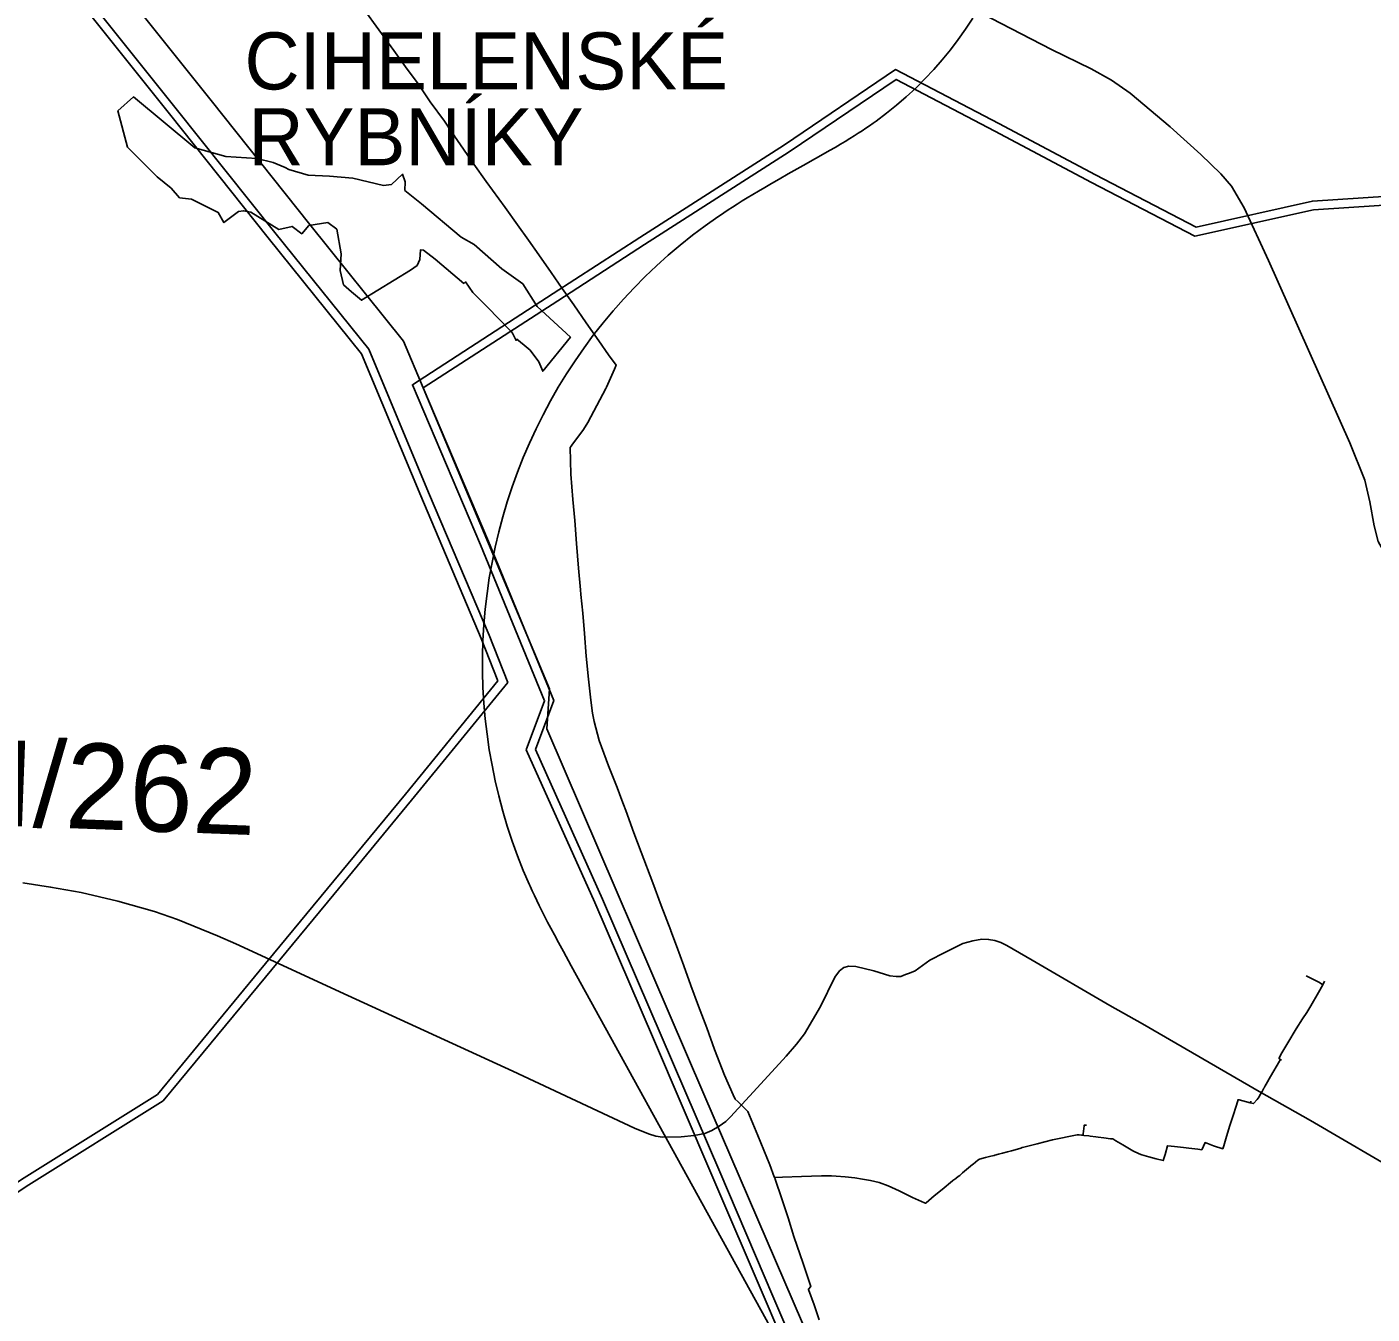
# Model space of a CAD drawing. Extents: x -789162 to -606354, y -1062736 to -945481.
# Drawn here: x -728880 to -726523, y -978118 to -975863 of the extents above; entities that cross this region are included whole.
import ezdxf

# ---------------------------------------------------------------- set-up
doc = ezdxf.new("R2010")
doc.units = 0
for name, color, linetype in [('_SIRSI VZTAHY_ELEKTRICKE VEDENI VN 110 kV N', 7, 'Continuous'), ('_SIRSI VZTAHY_ELEKTRICKE VEDENI VN 110 kV S', 7, 'Continuous'), ('_SIRSI VZTAHY_NATURA_EVL', 7, 'Continuous'), ('_SIRSI VZTAHY_NATURA_EVL_POPIS_KOD', 7, 'Continuous'), ('_SIRSI VZTAHY_SILNICE I TRIDY_NAVRH', 7, 'Continuous'), ('_SIRSI VZTAHY_SILNICE II TRIDY_STAV', 7, 'Continuous'), ('_SIRSI VZTAHY_SILNICE III TRIDY_STAV', 7, 'Continuous'), ('_SIRSI VZTAHY_SILNICE_STAV_POPIS', 7, 'Continuous'), ('_SIRSI VZTAHY_VTL PLYNOVOD', 7, 'Continuous')]:
    doc.layers.add(name, color=color, linetype=linetype)

msp = doc.modelspace()

# ---------------------------------------------------------------- linework, layer by layer
at = {"layer": '_SIRSI VZTAHY_ELEKTRICKE VEDENI VN 110 kV N'}
for points in [[(-730001.6, -974182.2), (-729926.4, -974276.7), (-729753.9, -974490.2), (-729579.2, -974709.3), (-729405.6, -974927.8), (-729235.3, -975141.2), (-729082, -975332.9), (-728912.9, -975546.4), (-728734.6, -975769.6), (-728557.1, -975992.1), (-728384.2, -976209.3), (-728219.7, -976413.6), (-728185.4, -976495.7)], [(-727043.5, -979221.4), (-727144.6, -978951.3), (-727261.2, -978729.6), (-727314.8, -978612.5), (-727442.5, -978315.6), (-727693.4, -977732.6), (-727968.8, -977092.7), (-727963.8, -977022.8), (-728185.4, -976495.7)]]:
    msp.add_lwpolyline(points, dxfattribs=at)
at = {"layer": '_SIRSI VZTAHY_ELEKTRICKE VEDENI VN 110 kV S'}
for points in [[(-728807.1, -975793.2), (-728629.6, -976015.7), (-728456.8, -976232.9), (-728293.4, -976435.6), (-728189.6, -976684.6), (-728083.6, -976934.7), (-728054.5, -977008.8)], [(-728795.4, -975783.9), (-728617.9, -976006.4), (-728445, -976223.5), (-728280.5, -976427.8), (-728175.9, -976678.6), (-728069.9, -976928.7), (-728036.8, -977011.8)], [(-725022.1, -976234.6), (-725022.2, -976234.6), (-725057, -976205.9), (-725103.2, -976186.7), (-725220.4, -976141.5), (-725361.8, -976086.8), (-725625.8, -976104.5), (-725922, -976124.3), (-726203.4, -976142), (-726405.2, -976153.7), (-726627.4, -976168.4), (-726831.3, -976213.7), (-727007.7, -976122.3), (-727177, -976032.2), (-727357.7, -975937.8), (-727552.2, -976069.5), (-727806, -976231.8), (-727957.6, -976330.3), (-728204.2, -976489.9), (-728084.9, -976770.4), (-727972.7, -977043.6), (-728004.9, -977129.4)], [(-725022.1, -976234.7), (-725022.2, -976234.7), (-725062.8, -976222.5), (-725109.1, -976200.4), (-725225.8, -976155.5), (-725364.1, -976102), (-725624.8, -976119.5), (-725921, -976139.3), (-726202.5, -976157), (-726404.2, -976168.7), (-726625.3, -976183.3), (-726833.4, -976229.5), (-727014.7, -976135.5), (-727184, -976045.5), (-727356.7, -975955.2), (-727544, -976082.1), (-727797.9, -976244.4), (-727949.5, -976342.9), (-728185.4, -976495.7), (-728071, -976764.6), (-727956.6, -977043.3), (-727988.7, -977129)], [(-728054.5, -977008.8), (-728216.6, -977207.2), (-728353.2, -977372.6), (-728472.7, -977517.6), (-728651, -977733.2), (-728884.3, -977879.2), (-729090.9, -978015.6), (-729298.2, -978150.3), (-729594, -978336.2), (-729816.7, -978480.8), (-730030.3, -978616.1), (-729984.7, -978878.1), (-729928.4, -979207.9), (-729879.9, -979486.1), (-730037.7, -979666.1), (-730181.7, -979830.4), (-730322.2, -979989.1), (-730471.5, -980157.9), (-730642.9, -980353.2), (-730823, -980555.3), (-731005.8, -980762.6), (-730973.3, -980973.9)], [(-728036.8, -977011.8), (-728205.6, -977217.5), (-728342.2, -977382.8), (-728461.7, -977527.7), (-728641.2, -977744.7), (-728876.1, -977891.8), (-729082.6, -978028.1), (-729289.9, -978162.8), (-729585.8, -978348.7), (-729808.5, -978493.3), (-730014, -978623.5), (-729969.9, -978875.8), (-729913.6, -979205.4), (-729864, -979490.8), (-730026.5, -979676.1), (-730170.4, -979840.4), (-730311, -979999.1), (-730460.3, -980167.9), (-730631.7, -980363.1), (-730811.7, -980565.1), (-730990.1, -980767.3), (-730957.1, -980982.4)], [(-727092.7, -979228.6), (-727080.3, -979163.2), (-727226.1, -978879.4), (-727350.5, -978612.4), (-727484, -978332), (-727586.5, -978092.8), (-727679.6, -977874.8), (-727782.1, -977635.9), (-727884.9, -977397), (-728004.9, -977129.4)], [(-727045.2, -979222.6), (-727045.2, -979222.7), (-727045.6, -979222.7), (-727046.3, -979224.3), (-727072.1, -979261.5), (-727076.9, -979225.8), (-727065.1, -979159.9), (-727212.6, -978872.9), (-727337, -978605.9), (-727470.4, -978325.8), (-727572.7, -978086.9), (-727665.8, -977868.9), (-727768.3, -977630), (-727871.2, -977391.1), (-727988.7, -977129)]]:
    msp.add_lwpolyline(points, dxfattribs=at)
at = {"layer": '_SIRSI VZTAHY_NATURA_EVL'}
msp.add_lwpolyline([(-728073.1, -976353.3), (-728030.5, -976397.6), (-728028.9, -976399.8), (-728022.6, -976412.4), (-728021.4, -976410.3), (-728008.5, -976420.4), (-727998, -976429.3), (-727982.8, -976449.6), (-727976, -976466.3), (-727927.4, -976406.7), (-727985.9, -976352.8), (-728010.6, -976313.3), (-728047.5, -976286.9), (-728095.8, -976244.2), (-728119, -976231.3), (-728188.1, -976173), (-728217.5, -976149.6), (-728216.7, -976134.8), (-728221.6, -976121.3), (-728241.1, -976139.4), (-728255.1, -976140.8), (-728308.8, -976128.3), (-728349.7, -976124.6), (-728386.9, -976123.1), (-728420.7, -976113.2), (-728427.3, -976109.2), (-728448.2, -976100.6), (-728477.1, -976093.9), (-728531.1, -976090.3), (-728585.4, -976075.2), (-728692.7, -975985.8), (-728720.5, -976010.1), (-728703.3, -976073.9), (-728651.7, -976126), (-728626.9, -976145.4), (-728612.1, -976162.6), (-728591.5, -976165), (-728544.3, -976188.5), (-728534.5, -976205.9), (-728509, -976186.6), (-728500, -976185.1), (-728487.5, -976187.9), (-728438.1, -976217.9), (-728415.1, -976212.6), (-728398.2, -976225.6), (-728385.6, -976210.9), (-728352.4, -976205.7), (-728336.8, -976217.7), (-728329, -976260.6), (-728330.7, -976289.7), (-728325.1, -976314.7), (-728310.7, -976327.1), (-728293.2, -976341.9), (-728207.5, -976289.1), (-728196, -976281.3), (-728191.3, -976270.7), (-728189.9, -976253.5), (-728184.7, -976254), (-728164.4, -976270.2), (-728114, -976312.4), (-728111, -976310), (-728098.2, -976328.2)], close=True, dxfattribs=at)
at = {"layer": '_SIRSI VZTAHY_SILNICE I TRIDY_NAVRH'}
msp.add_lwpolyline([(-727222.6, -975847.9), (-727235, -975866.8), (-727248, -975885.3), (-727261.7, -975903.3), (-727276, -975920.8), (-727290.9, -975937.8), (-727306.4, -975954.3), (-727322.4, -975970.2), (-727339, -975985.5), (-727356.1, -976000.3), (-727373.7, -976014.5), (-727391.8, -976028), (-727397.3, -976031.9), (-727403.4, -976036.2), (-727409.8, -976040.6), (-727416.4, -976045), (-727423.3, -976049.5), (-727430.4, -976054), (-727437.9, -976058.8), (-727445.9, -976063.6), (-727454.3, -976068.7), (-727463.4, -976074.1), (-727473.3, -976079.9), (-727484.5, -976086.3), (-727497.9, -976093.9), (-727519.7, -976106.1), (-727545.7, -976120.7), (-727561.8, -976129.8), (-727575.2, -976137.4), (-727587, -976144.3), (-727597.9, -976150.7), (-727608, -976156.7), (-727617.5, -976162.5), (-727626.5, -976168), (-727635.1, -976173.4), (-727643.4, -976178.7), (-727651.3, -976183.8), (-727658.9, -976188.9), (-727666.3, -976193.9), (-727669.2, -976195.8), (-727691.6, -976211.7), (-727713.6, -976228.2), (-727735.1, -976245.4), (-727756, -976263.2), (-727776.5, -976281.5), (-727796.4, -976300.5), (-727815.8, -976320), (-727834.5, -976340.1), (-727852.7, -976360.7), (-727870.3, -976381.8), (-727887.3, -976403.4), (-727903.6, -976425.5), (-727919.3, -976448.1), (-727934.3, -976471.1), (-727948.7, -976494.5), (-727962.4, -976518.4), (-727975.3, -976542.6), (-727987.6, -976567.2), (-727999.2, -976592.1), (-728010, -976617.4), (-728020.1, -976643), (-728029.4, -976668.8), (-728038, -976694.9), (-728045.9, -976721.2), (-728053, -976747.8), (-728059.3, -976774.6), (-728064.8, -976801.5), (-728069.5, -976828.5), (-728073.5, -976855.7), (-728076.7, -976883), (-728079, -976910.4), (-728080.6, -976937.9), (-728081.4, -976965.3), (-728081.4, -976992.8), (-728080.6, -977020.3), (-728079, -977047.7), (-728076.7, -977075.1), (-728073.5, -977102.4), (-728069.5, -977129.6), (-728064.8, -977156.7), (-728059.2, -977183.6), (-728052.9, -977210.4), (-728045.9, -977236.9), (-728038, -977263.3), (-728029.4, -977289.4), (-728020.1, -977315.2), (-728010, -977340.8), (-727999.1, -977366), (-727998.1, -977368.4), (-727994.4, -977376.5), (-727990.5, -977384.9), (-727986.4, -977393.4), (-727982.1, -977402.3), (-727977.5, -977411.5), (-727972.6, -977421.2), (-727967.4, -977431.3), (-727961.7, -977442.2), (-727955.5, -977453.9), (-727948.4, -977467.1), (-727939.8, -977482.8), (-727925.9, -977508.2), (-727399.4, -978463.4)], dxfattribs=at)
at = {"layer": '_SIRSI VZTAHY_SILNICE II TRIDY_STAV'}
msp.add_lwpolyline([(-726460.9, -977878), (-726630.6, -977779.2), (-726720.9, -977728.4), (-726925.1, -977609.8), (-726982.4, -977577.5), (-727118.3, -977497.9), (-727162.6, -977472.1), (-727173.3, -977466.9), (-727184.1, -977463.7), (-727194.7, -977461.8), (-727206.4, -977461.4), (-727222.4, -977464.2), (-727240.1, -977469.1), (-727272.6, -977485.1), (-727298, -977498.2), (-727323.2, -977516.5), (-727333.2, -977520.6), (-727340.2, -977523.4), (-727348.8, -977526.5), (-727356.6, -977526.8), (-727368.1, -977525.3), (-727395.8, -977516.6), (-727427.4, -977509), (-727439.4, -977508.7), (-727448.2, -977511.1), (-727456, -977516.5), (-727464.4, -977528), (-727489.1, -977579.2), (-727517.4, -977627.3), (-727531.2, -977645.1), (-727549.7, -977666.2), (-727600.2, -977721.5), (-727647, -977772.4), (-727655.4, -977780.7), (-727666.7, -977788.7), (-727679.5, -977796.4), (-727691.7, -977801.6), (-727710.9, -977805.2), (-727733.4, -977807.5), (-727766.3, -977807.9), (-727778, -977806.1), (-727790.4, -977802.2), (-727815.4, -977792.3), (-728028.1, -977692.7), (-728317.4, -977559.9), (-728513.8, -977469.6), (-728545.5, -977455.6), (-728616, -977426.9), (-728656.2, -977412.9), (-728720.5, -977394.6), (-728784.6, -977379.6), (-728838.2, -977370), (-728886.8, -977362.3)], dxfattribs=at)
at = {"layer": '_SIRSI VZTAHY_SILNICE III TRIDY_STAV'}
msp.add_lwpolyline([(-727226, -975829.8), (-727084.3, -975902.6), (-727015, -975936.8), (-726979.4, -975956.2), (-726946.6, -975979.2), (-726876.7, -976038.4), (-726823.2, -976086.6), (-726788.1, -976120.4), (-726769.1, -976142.4), (-726746.8, -976179.9), (-726704.2, -976272.2), (-726562.2, -976591.7), (-726535.4, -976657.2), (-726526.7, -976694.9), (-726519.5, -976736.9), (-726512.2, -976764.7), (-726498.9, -976788.6), (-726463.7, -976828.5), (-726425.6, -976870), (-726387.7, -976903.2), (-726199.4, -977071.6), (-726010.4, -977249.1), (-725963.6, -977296.5), (-725896.6, -977368.5)], dxfattribs=at)
at = {"layer": '_SIRSI VZTAHY_VTL PLYNOVOD'}
for points in [[(-728289.2, -975832), (-728263.1, -975868), (-728237, -975904.4), (-728216.6, -975933), (-728194.4, -975962.9), (-728172.9, -975994.1), (-728148, -976028.3), (-728135.7, -976046.7), (-728130.7, -976054.2), (-728130.5, -976054.5), (-728120.1, -976069.9), (-728096.6, -976103.3), (-728075.1, -976133.7), (-728041.6, -976179.7), (-728020.3, -976209.8), (-728001.1, -976237), (-727982.6, -976262.6), (-727961.4, -976293.1), (-727941.7, -976321.5), (-727921.5, -976349.9), (-727899.9, -976381.3), (-727877.9, -976413), (-727860.7, -976437.4), (-727847.4, -976455.9), (-727850.4, -976462.9), (-727864.1, -976494.2), (-727865.4, -976496.7), (-727897.1, -976556.1), (-727904.7, -976568.5), (-727924.7, -976595.8), (-727926, -976597.6), (-727927.9, -976600.1), (-727926.7, -976646.7), (-727923.2, -976690.8), (-727919.8, -976727.7), (-727916.7, -976768), (-727913.1, -976811.1), (-727909.6, -976849.4), (-727908.9, -976857.2), (-727905.7, -976889.9), (-727902.6, -976925.7), (-727900, -976965.4), (-727895.8, -977005.7), (-727891.5, -977042.5), (-727888.5, -977065.2), (-727886, -977080), (-727877, -977113.4), (-727860.8, -977157.8), (-727845.8, -977195.8), (-727837.2, -977218), (-727834.5, -977225.1), (-727830.4, -977235.8), (-727816.1, -977274.9), (-727803.4, -977308.9), (-727783.1, -977362.5), (-727768.3, -977402.2), (-727751.6, -977446), (-727751.3, -977446.8), (-727741.7, -977472.8), (-727728.8, -977507.9), (-727716.4, -977542.2), (-727703, -977578.8), (-727688.6, -977616.8), (-727674.9, -977654.8), (-727657.7, -977699.4), (-727642.2, -977734.1), (-727638.6, -977741.4), (-727633.8, -977746.1), (-727630.7, -977749.1), (-727625.4, -977754.3), (-727624.2, -977755.5), (-727624.1, -977755.7), (-727624.1, -977755.7), (-727618.3, -977761.2), (-727616.6, -977763.4), (-727599.2, -977805), (-727578.1, -977856.5), (-727570.2, -977877.8), (-727570.2, -977877.9), (-727570.1, -977878.1), (-727570, -977878.5), (-727569.9, -977878.7), (-727569.8, -977878.9)], [(-726683.5, -977672.1), (-726684.4, -977671.6), (-726685, -977671.3), (-726686.3, -977670.6), (-726686.2, -977670.3), (-726686, -977670), (-726685.7, -977669.4), (-726685.5, -977669), (-726680.8, -977660.3), (-726667.2, -977637), (-726659.4, -977624.3), (-726655.9, -977618.5), (-726644.8, -977601.1), (-726637.2, -977589.6), (-726630.1, -977578), (-726616.7, -977554.6), (-726609.4, -977541)], [(-726614.8, -977537.6), (-726615.3, -977537.3), (-726638.4, -977525.5), (-726638.7, -977525.4)], [(-726614.8, -977537.6), (-726614.5, -977537.2), (-726614.1, -977537.5), (-726613.8, -977537.7), (-726613.7, -977537.8), (-726614, -977538.2)], [(-726614.8, -977537.6), (-726614.4, -977537.9), (-726614.2, -977538), (-726614, -977538.2)], [(-726609.4, -977541), (-726613.6, -977538.5), (-726614, -977538.2)], [(-726609.4, -977541), (-726606.1, -977535.1)], [(-726736.4, -977747.9), (-726730.6, -977749.4), (-726724.1, -977741.9), (-726722.7, -977740.1), (-726721.9, -977739), (-726721.3, -977738.1), (-726721, -977737.6), (-726720, -977735.9), (-726715.6, -977728.1), (-726712.5, -977722.5), (-726711.7, -977721.3), (-726711.3, -977720.7), (-726710.1, -977718.3), (-726708.3, -977715.1), (-726701, -977701.9), (-726685.1, -977674.8), (-726684.6, -977673.9), (-726683.8, -977672.5), (-726683.6, -977672.3), (-726683.5, -977672.1)], [(-726683.5, -977672.1), (-726682.7, -977672.5), (-726682, -977672.8), (-726681.8, -977672.9), (-726681.7, -977672.9)], [(-727029.5, -977804.8), (-727029.2, -977804.8), (-727029, -977804.9), (-727028.5, -977804.9), (-727027.7, -977805), (-727019.2, -977806), (-727019.2, -977806), (-727016.8, -977806.3), (-727006.9, -977807.5), (-727002.9, -977808.1), (-726992.9, -977809.3), (-726981.3, -977810.8), (-726977.1, -977811), (-726975.1, -977812.2), (-726971.6, -977814.3), (-726959.8, -977821.4), (-726942.1, -977832), (-726931.1, -977837.6), (-726926.5, -977839.1), (-726913.8, -977842.8), (-726901.2, -977846), (-726888.7, -977849.3), (-726885.6, -977838.5), (-726881.3, -977823.1), (-726880.9, -977823.2), (-726868.9, -977824.3), (-726853.2, -977826.5), (-726843.9, -977827.5), (-726828.4, -977829.3), (-726821.3, -977830.2), (-726815.4, -977817.5), (-726800.8, -977823.1), (-726784.6, -977828.5), (-726782.8, -977823.5), (-726779.2, -977810.8), (-726772.6, -977789.6), (-726766.8, -977772.2), (-726760.6, -977752), (-726757.5, -977742.2), (-726756.7, -977742.5), (-726756, -977742.9), (-726736.4, -977747.9)], [(-726736.4, -977747.9), (-726735.6, -977745.5), (-726735.5, -977745.1)], [(-727568.6, -977879), (-727568.2, -977878.8), (-727567.7, -977878.6), (-727555.9, -977878.4), (-727522.3, -977877.2), (-727487.7, -977875.8), (-727481.1, -977875.9), (-727470.3, -977876.1), (-727461.8, -977876.6), (-727446, -977877.7), (-727429.2, -977879.5), (-727415.9, -977881.5), (-727401.7, -977884.1), (-727386.4, -977887.8), (-727370.9, -977893.5), (-727351.7, -977902.4), (-727327.9, -977913.6), (-727307.2, -977923.2), (-727305.5, -977924), (-727304.3, -977923.4), (-727290.3, -977911), (-727275.9, -977899.9), (-727258, -977884.9), (-727257.6, -977884.7), (-727257.2, -977884.3), (-727252.3, -977880.4), (-727251.5, -977879.8), (-727247.9, -977876.9), (-727245.4, -977875), (-727241.9, -977871.9), (-727241.3, -977871.4), (-727240.6, -977870.9), (-727240.5, -977870.9), (-727222.8, -977856.1), (-727221.6, -977855.2), (-727213.4, -977848.5), (-727210.9, -977846.5), (-727200.5, -977843.9), (-727193, -977842), (-727185.6, -977840.2), (-727185, -977840), (-727184.1, -977839.8), (-727177.7, -977838), (-727170.7, -977836.1), (-727170.6, -977836.1), (-727161.6, -977833.7), (-727154.5, -977831.8), (-727140, -977827.8), (-727139.9, -977827.8), (-727138.4, -977827.3), (-727135.9, -977826.5), (-727133.2, -977825.9), (-727109.7, -977819.8), (-727083, -977812.6), (-727083, -977812.6), (-727039.6, -977804), (-727035.9, -977804), (-727032, -977804.5), (-727030.2, -977804.7), (-727029.9, -977804.7)], [(-727029.5, -977804.6), (-727029.9, -977804.6), (-727029.9, -977804.7), (-727029.9, -977804.7)], [(-727029.9, -977804.7), (-727029.5, -977804.8)], [(-727023.2, -977787.2), (-727024, -977787.2), (-727024, -977787.2), (-727024.1, -977787.2), (-727024.4, -977787.1), (-727025.2, -977787.1), (-727026.2, -977787), (-727027.3, -977786.9), (-727027.5, -977788.5), (-727029.3, -977802.4), (-727029.3, -977803.7), (-727029.5, -977804.6)], [(-727029.5, -977804.6), (-727029.5, -977804.7), (-727029.5, -977804.8)], [(-727569.8, -977878.9), (-727569.5, -977878.8)], [(-727569.8, -977878.9), (-727569.6, -977879.5), (-727569.4, -977880)], [(-727569.5, -977878.8), (-727569.2, -977878.7), (-727568.8, -977878.5), (-727568.6, -977879)], [(-727569.5, -977878.8), (-727569.5, -977879), (-727569.3, -977879.3)], [(-727569.4, -977880), (-727569.1, -977879.9)], [(-727491.4, -978128.2), (-727500.3, -978102.1), (-727510.2, -978074.8), (-727510.2, -978074.4), (-727506, -978069.9), (-727519.9, -978029.2), (-727535.8, -977981.9), (-727546, -977949.7), (-727557.1, -977916.1), (-727568.8, -977881.6), (-727568.8, -977881.6), (-727568.9, -977881.4), (-727569.3, -977880.4), (-727569.4, -977880)], [(-727569.3, -977879.3), (-727569, -977879.2), (-727568.6, -977879.1)], [(-727569.3, -977879.3), (-727569.2, -977879.6), (-727569.1, -977879.9)], [(-727569.1, -977879.9), (-727568.7, -977879.7), (-727568.4, -977879.6), (-727568.6, -977879.1)], [(-727568.6, -977879), (-727568.6, -977879.1)]]:
    msp.add_lwpolyline(points, dxfattribs=at)

# ---------------------------------------------------------------- texts
at = {"layer": '_SIRSI VZTAHY_NATURA_EVL_POPIS_KOD'}
for s, p in [('CIHELENSKÉ', (-728498.4, -975972.7)), ('RYBNÍKY', (-728491.4, -976105.5))]:
    msp.add_text(s, height=100, dxfattribs=at).set_placement(p)
at = {"layer": '_SIRSI VZTAHY_SILNICE_STAV_POPIS'}
msp.add_text('II/262', height=150, rotation=357.8491, dxfattribs=at).set_placement((-728981.2, -977260.2))

doc.saveas('drawing.dxf')
